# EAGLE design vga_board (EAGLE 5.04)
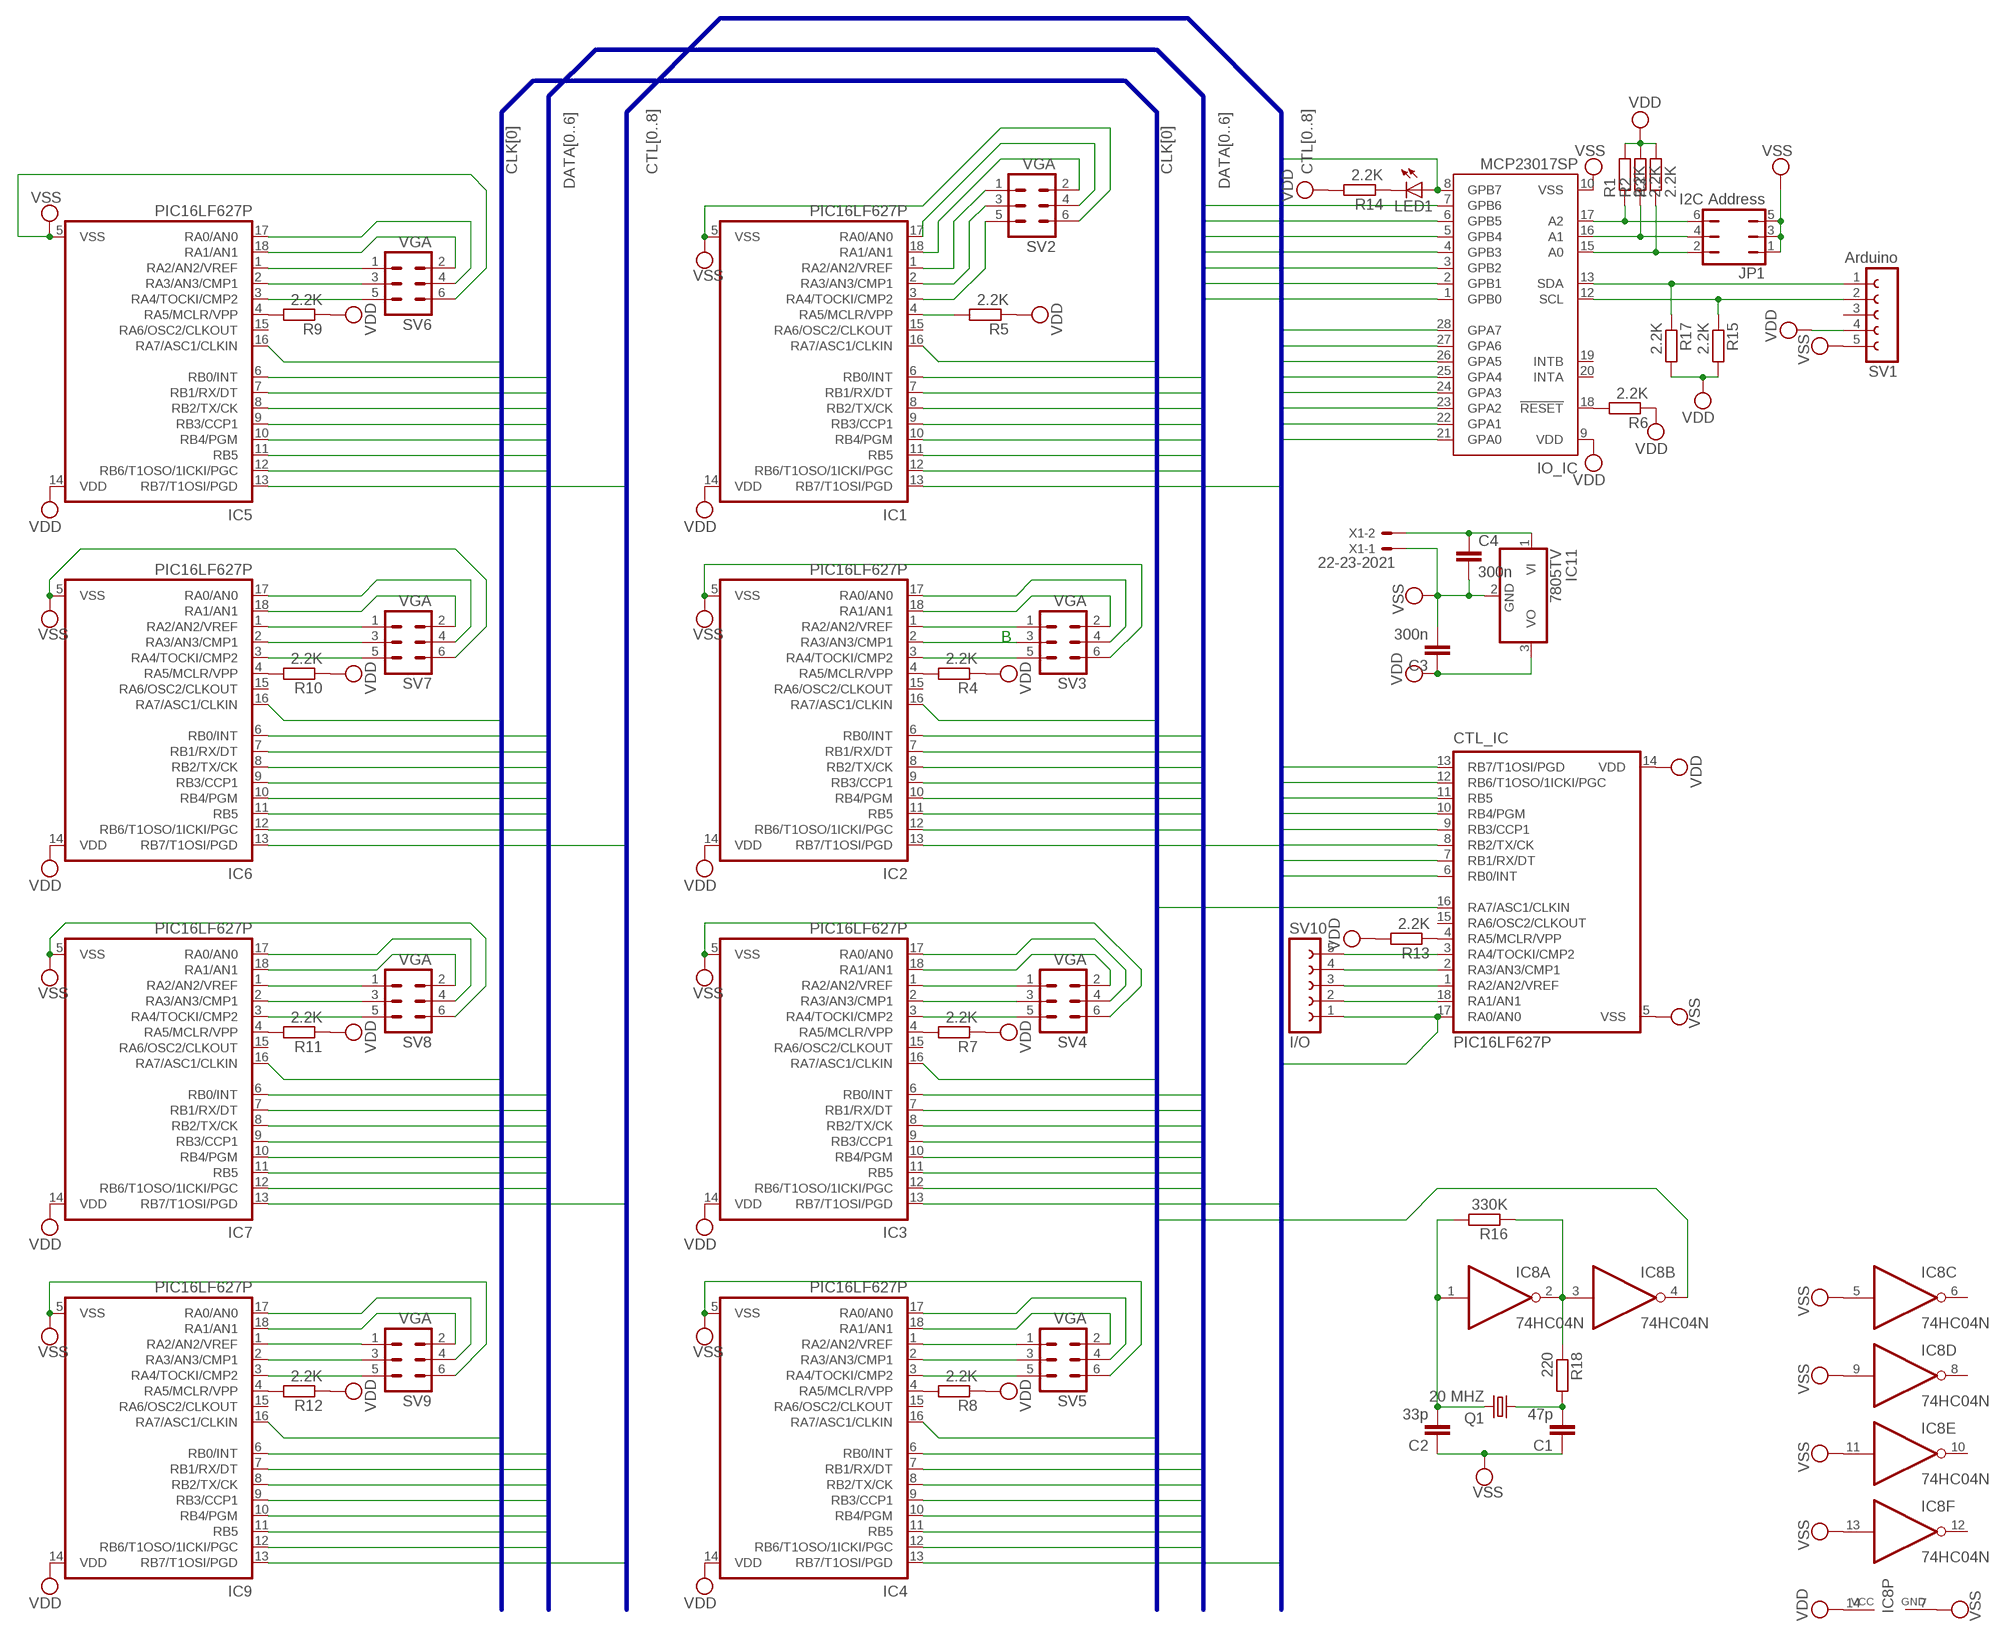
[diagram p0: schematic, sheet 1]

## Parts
C1  47p  C-EU025-024X044  [C025-024X044]
C2  33p  C-EU025-024X044  [C025-024X044]
C3  300n  C-EU025-024X044  [C025-024X044]
C4  300n  C-EU025-024X044  [C025-024X044]
CTL_IC  PIC16LF627P  [DIL18]
IC1  PIC16LF627P  [DIL18]
IC2  PIC16LF627P  [DIL18]
IC3  PIC16LF627P  [DIL18]
IC4  PIC16LF627P  [DIL18]
IC5  PIC16LF627P  [DIL18]
IC6  PIC16LF627P  [DIL18]
IC7  PIC16LF627P  [DIL18]
IC8  74HC04N  [DIL14]
IC9  PIC16LF627P  [DIL18]
IC11  7805TV  [TO220V]
IO_IC  MCP23017SP  [DIL28-3]
JP1  I2C Address  JP3Q  [JP3Q]
LED1  LED3MM  [LED3MM]
Q1  20 MHZ  CRYSTALHC18U-V  [HC18U-V]
R1  2.2K  R-EU_0204/7  [0204/7]
R2  2.2K  R-EU_0204/7  [0204/7]
R3  2.2K  R-EU_0204/7  [0204/7]
R4  2.2K  R-EU_0207/2V  [0207/2V]
R5  2.2K  R-EU_0207/2V  [0207/2V]
R6  2.2K  R-EU_0204/7  [0204/7]
R7  2.2K  R-EU_0207/2V  [0207/2V]
R8  2.2K  R-EU_0207/2V  [0207/2V]
R9  2.2K  R-EU_0207/2V  [0207/2V]
R10  2.2K  R-EU_0207/2V  [0207/2V]
R11  2.2K  R-EU_0207/2V  [0207/2V]
R12  2.2K  R-EU_0207/2V  [0207/2V]
R13  2.2K  R-EU_0207/2V  [0207/2V]
R14  2.2K  R-EU_0204/7  [0204/7]
R15  2.2K  R-EU_0207/2V  [0207/2V]
R16  330K  R-EU_0207/2V  [0207/2V]
R17  2.2K  R-EU_0207/2V  [0207/2V]
R18  220  R-EU_0207/2V  [0207/2V]
SV1  Arduino  FE05-1  [FE05-1]
SV2  VGA  MA03-2  [MA03-2]
SV3  VGA  MA03-2  [MA03-2]
SV4  VGA  MA03-2  [MA03-2]
SV5  VGA  MA03-2  [MA03-2]
SV6  VGA  MA03-2  [MA03-2]
SV7  VGA  MA03-2  [MA03-2]
SV8  VGA  MA03-2  [MA03-2]
SV9  VGA  MA03-2  [MA03-2]
SV10  I/O  FE05-1  [FE05-1]
X1  22-23-2021  [22-23-2021]

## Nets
CLK0: CTL_IC.16(RA7/ASC1/CLKIN) IC1.16(RA7/ASC1/CLKIN) IC2.16(RA7/ASC1/CLKIN) IC3.16(RA7/ASC1/CLKIN) IC4.16(RA7/ASC1/CLKIN) IC5.16(RA7/ASC1/CLKIN) IC6.16(RA7/ASC1/CLKIN) IC7.16(RA7/ASC1/CLKIN) IC8.4(B:O) IC9.16(RA7/ASC1/CLKIN)
CTL0: CTL_IC.6(RB0/INT) IC1.13(RB7/T1OSI/PGD) IO_IC.21(GPA0)
CTL1: CTL_IC.7(RB1/RX/DT) IC2.13(RB7/T1OSI/PGD) IO_IC.22(GPA1)
CTL2: CTL_IC.8(RB2/TX/CK) IC3.13(RB7/T1OSI/PGD) IO_IC.23(GPA2)
CTL3: CTL_IC.9(RB3/CCP1) IC4.13(RB7/T1OSI/PGD) IO_IC.24(GPA3)
CTL4: CTL_IC.10(RB4/PGM) IC5.13(RB7/T1OSI/PGD) IO_IC.25(GPA4)
CTL5: CTL_IC.11(RB5) IC6.13(RB7/T1OSI/PGD) IO_IC.26(GPA5)
CTL6: CTL_IC.12(RB6/T1OSO/1ICKI/PGC) IC7.13(RB7/T1OSI/PGD) IO_IC.27(GPA6)
CTL7: CTL_IC.13(RB7/T1OSI/PGD) IC9.13(RB7/T1OSI/PGD) IO_IC.28(GPA7)
CTL8: CTL_IC.17(RA0/AN0) IO_IC.8(GPB7) LED1.A SV10.1
DATA0: IC1.6(RB0/INT) IC2.6(RB0/INT) IC3.6(RB0/INT) IC4.6(RB0/INT) IC5.6(RB0/INT) IC6.6(RB0/INT) IC7.6(RB0/INT) IC9.6(RB0/INT) IO_IC.1(GPB0)
DATA1: IC1.7(RB1/RX/DT) IC2.7(RB1/RX/DT) IC3.7(RB1/RX/DT) IC4.7(RB1/RX/DT) IC5.7(RB1/RX/DT) IC6.7(RB1/RX/DT) IC7.7(RB1/RX/DT) IC9.7(RB1/RX/DT) IO_IC.2(GPB1)
DATA2: IC1.8(RB2/TX/CK) IC2.8(RB2/TX/CK) IC3.8(RB2/TX/CK) IC4.8(RB2/TX/CK) IC5.8(RB2/TX/CK) IC6.8(RB2/TX/CK) IC7.8(RB2/TX/CK) IC9.8(RB2/TX/CK) IO_IC.3(GPB2)
DATA3: IC1.9(RB3/CCP1) IC2.9(RB3/CCP1) IC3.9(RB3/CCP1) IC4.9(RB3/CCP1) IC5.9(RB3/CCP1) IC6.9(RB3/CCP1) IC7.9(RB3/CCP1) IC9.9(RB3/CCP1) IO_IC.4(GPB3)
DATA4: IC1.10(RB4/PGM) IC2.10(RB4/PGM) IC3.10(RB4/PGM) IC4.10(RB4/PGM) IC5.10(RB4/PGM) IC6.10(RB4/PGM) IC7.10(RB4/PGM) IC9.10(RB4/PGM) IO_IC.5(GPB4)
DATA5: IC1.11(RB5) IC2.11(RB5) IC3.11(RB5) IC4.11(RB5) IC5.11(RB5) IC6.11(RB5) IC7.11(RB5) IC9.11(RB5) IO_IC.6(GPB5)
DATA6: IC1.12(RB6/T1OSO/1ICKI/PGC) IC2.12(RB6/T1OSO/1ICKI/PGC) IC3.12(RB6/T1OSO/1ICKI/PGC) IC4.12(RB6/T1OSO/1ICKI/PGC) IC5.12(RB6/T1OSO/1ICKI/PGC) IC6.12(RB6/T1OSO/1ICKI/PGC) IC7.12(RB6/T1OSO/1ICKI/PGC) IC9.12(RB6/T1OSO/1ICKI/PGC) IO_IC.7(GPB6)
IC8: IC9.2(RA3/AN3/CMP1) SV9.3
N$1: IO_IC.17(A2) JP1.6 R1.1
N$2: IO_IC.16(A1) JP1.4 R2.1
N$3: IO_IC.15(A0) JP1.2 R3.1
N$4: IC2.4(RA5/MCLR/VPP) R4.2
N$5: IO_IC.13(SDA) R17.1 SV1.1
N$6: IC2.3(RA4/TOCKI/CMP2) SV3.5
N$7: C1.2 Q1.1 R18.2
N$8: IO_IC.18(!RESET) R6.2
N$9: IO_IC.12(SCL) R15.1 SV1.2
N$10: IC1.4(RA5/MCLR/VPP) R5.2
N$11: IC1.3(RA4/TOCKI/CMP2) SV2.5
N$12: IC1.2(RA3/AN3/CMP1) SV2.3
N$13: IC1.1(RA2/AN2/VREF) SV2.1
N$14: IC1.18(RA1/AN1) SV2.2
N$15: IC2.2(RA3/AN3/CMP1) SV3.3
N$16: IC2.1(RA2/AN2/VREF) SV3.1
N$17: IC2.18(RA1/AN1) SV3.2
N$18: IC2.17(RA0/AN0) SV3.4
N$19: IC3.4(RA5/MCLR/VPP) R7.2
N$20: IC3.3(RA4/TOCKI/CMP2) SV4.5
N$21: IC3.2(RA3/AN3/CMP1) SV4.3
N$22: IC3.1(RA2/AN2/VREF) SV4.1
N$23: IC3.18(RA1/AN1) SV4.2
N$24: IC3.17(RA0/AN0) SV4.4
N$25: IC4.4(RA5/MCLR/VPP) R8.2
N$26: IC4.3(RA4/TOCKI/CMP2) SV5.5
N$27: IC4.2(RA3/AN3/CMP1) SV5.3
N$28: IC4.1(RA2/AN2/VREF) SV5.1
N$29: IC4.18(RA1/AN1) SV5.2
N$30: IC4.17(RA0/AN0) SV5.4
N$31: IC5.4(RA5/MCLR/VPP) R9.2
N$32: CTL_IC.4(RA5/MCLR/VPP) R13.1
N$33: IC5.3(RA4/TOCKI/CMP2) SV6.5
N$34: IC5.2(RA3/AN3/CMP1) SV6.3
N$35: IC5.1(RA2/AN2/VREF) SV6.1
N$36: IC5.18(RA1/AN1) SV6.2
N$37: IC6.4(RA5/MCLR/VPP) R10.2
N$38: IC6.3(RA4/TOCKI/CMP2) SV7.5
N$39: IC6.2(RA3/AN3/CMP1) SV7.3
N$40: IC6.1(RA2/AN2/VREF) SV7.1
N$41: IC6.18(RA1/AN1) SV7.2
N$42: IC6.17(RA0/AN0) SV7.4
N$43: IC7.4(RA5/MCLR/VPP) R11.2
N$44: IC7.3(RA4/TOCKI/CMP2) SV8.5
N$45: IC7.2(RA3/AN3/CMP1) SV8.3
N$46: IC7.1(RA2/AN2/VREF) SV8.1
N$47: IC7.18(RA1/AN1) SV8.2
N$48: IC7.17(RA0/AN0) SV8.4
N$49: IC9.4(RA5/MCLR/VPP) R12.2
N$50: IC9.3(RA4/TOCKI/CMP2) SV9.5
N$51: C2.2 IC8.1(A:I) Q1.2 R16.2
N$52: IC9.1(RA2/AN2/VREF) SV9.1
N$53: IC9.18(RA1/AN1) SV9.2
N$54: IC9.17(RA0/AN0) SV9.4
N$55: IC5.17(RA0/AN0) SV6.4
N$56: IC8.2(A:O) IC8.3(B:I) R16.1 R18.1
N$57: CTL_IC.18(RA1/AN1) SV10.2
N$58: CTL_IC.1(RA2/AN2/VREF) SV10.3
N$59: CTL_IC.2(RA3/AN3/CMP1) SV10.4
N$60: CTL_IC.3(RA4/TOCKI/CMP2) SV10.5
N$61 [high]: C4.1 IC11.1(VI) X1.2
N$62: LED1.K(C) R14.1
N$68: IC1.17(RA0/AN0) SV2.4
VDD: C3.1 CTL_IC.14(VDD) IC1.14(VDD) IC2.14(VDD) IC3.14(VDD) IC4.14(VDD) IC5.14(VDD) IC6.14(VDD) IC7.14(VDD) IC8.14(P:VCC) IC9.14(VDD) IC11.3(VO) IO_IC.9(VDD) R1.2 R2.2 R3.2 R4.1 R5.1 R6.1 R7.1 R8.1 R9.1 R10.1 R11.1 R12.1 R13.2 R14.2 R15.2 R17.2 SV1.4
VSS: C1.1 C2.1 C3.2 C4.2 CTL_IC.5(VSS) IC1.5(VSS) IC2.5(VSS) IC3.5(VSS) IC4.5(VSS) IC5.5(VSS) IC6.5(VSS) IC7.5(VSS) IC8.5(C:I) IC8.7(P:GND) IC8.9(D:I) IC8.11(E:I) IC8.13(F:I) IC9.5(VSS) IC11.2(GND) IO_IC.10(VSS) JP1.1 JP1.3 JP1.5 SV1.5 SV2.6 SV3.6 SV4.6 SV5.6 SV6.6 SV7.6 SV8.6 SV9.6 X1.1
Unconnected: CTL_IC.15(RA6/OSC2/CLKOUT) IC1.15(RA6/OSC2/CLKOUT) IC2.15(RA6/OSC2/CLKOUT) IC3.15(RA6/OSC2/CLKOUT) IC4.15(RA6/OSC2/CLKOUT) IC5.15(RA6/OSC2/CLKOUT) IC6.15(RA6/OSC2/CLKOUT) IC7.15(RA6/OSC2/CLKOUT) IC8.6(C:O) IC8.8(D:O) IC8.10(E:O) IC8.12(F:O) IC9.15(RA6/OSC2/CLKOUT) IO_IC.19(INTB) IO_IC.20(INTA) SV1.3

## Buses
DATA[0..6]
CTL[0..8]
CLK[0]

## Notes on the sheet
- B

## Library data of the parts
C1-C4 = rcl:C-EU: CAPACITOR, European symbol
CTL_IC IC1-IC7 IC9 = microchip:PIC16*F62: FLASH-Based 8-Bit CMOS Microcontroller Source: http://ww1.microchip.com/downloads/en/DeviceDoc/40300C.pdf
IC8 = 74xx-eu:74*04: Hex INVERTER
IC11 = linear:78*: Positive VOLTAGE REGULATOR Source: http://cache.national.com/ds/LM/LM78L05.pdf http://www.fairchildsemi.com/ds/LM/LM7805.pdf
IO_IC = microchip:MCP23017: http://ww1.microchip.com/downloads/en/DeviceDoc/21952a.pdf Source: http://ww1.microchip.com/downloads/en/DeviceDoc/21952a.pdf
JP1 = jumper:JP3Q: JUMPER
LED1 = led:LED: LED
Q1 = crystal:CRYSTAL: CRYSTAL
R1-R18 = resistor:R-EU_: RESISTOR, European symbol
SV1 SV10 = con-lsta:FE05-1: FEMALE HEADER
SV2-SV9 = con-lstb:MA03-2: PIN HEADER
X1 = con-molex:22-23-2021: .100" (2.54mm) Center Header - 2 Pin

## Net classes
1 high: width 1.016 mm, clearance 0.508 mm

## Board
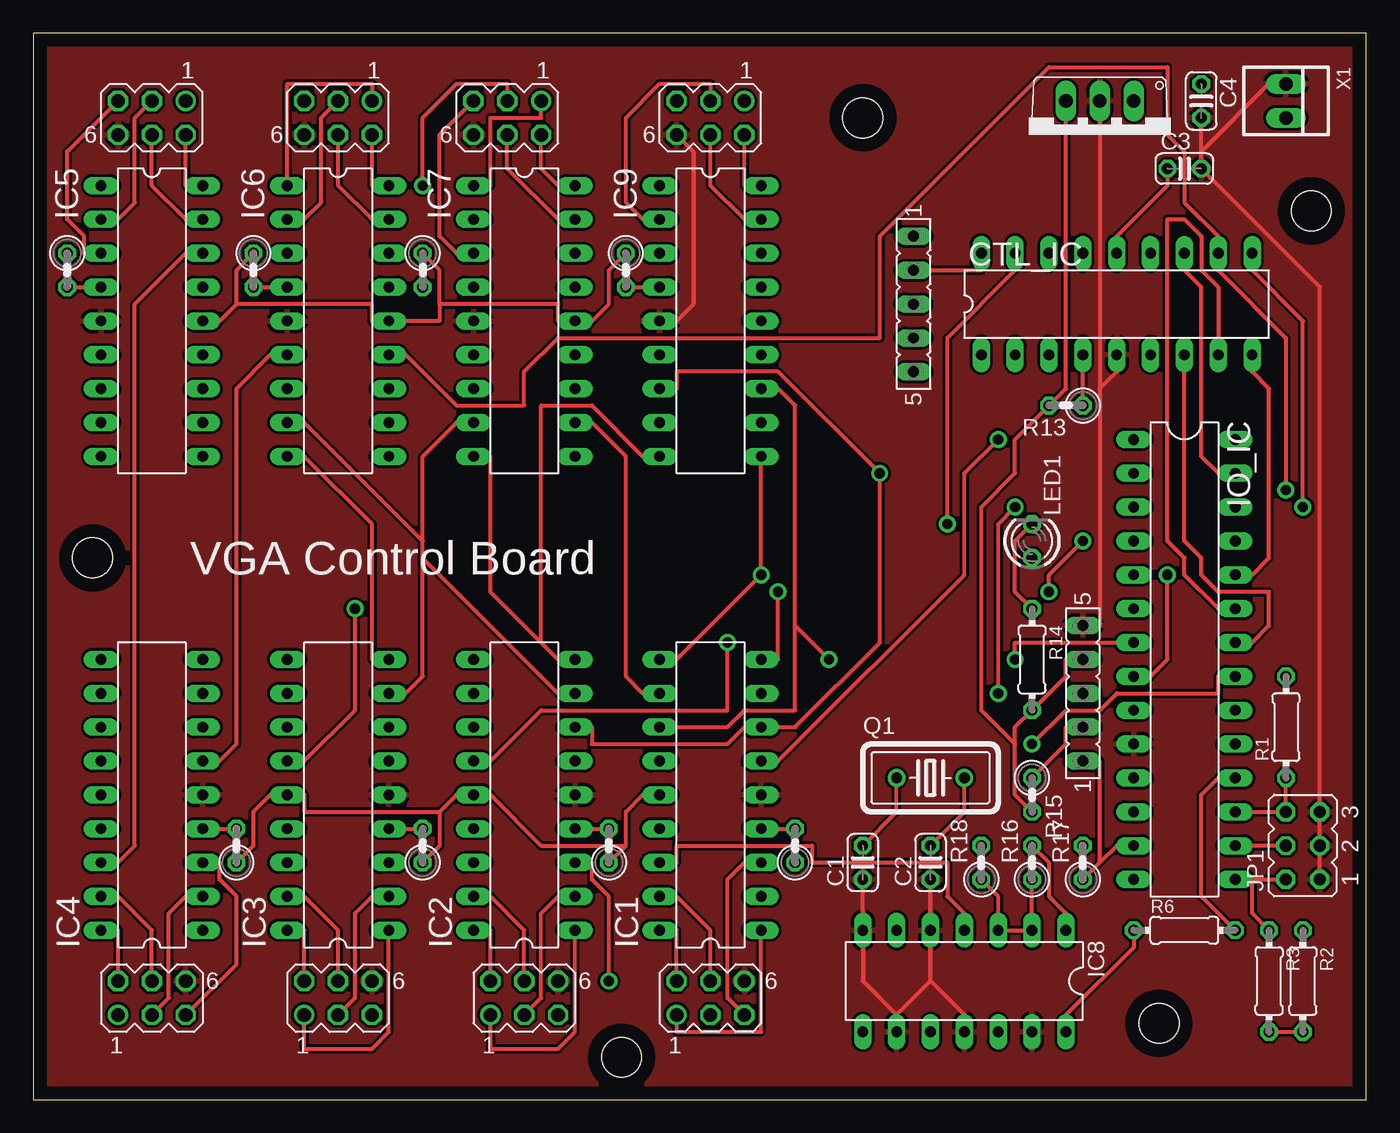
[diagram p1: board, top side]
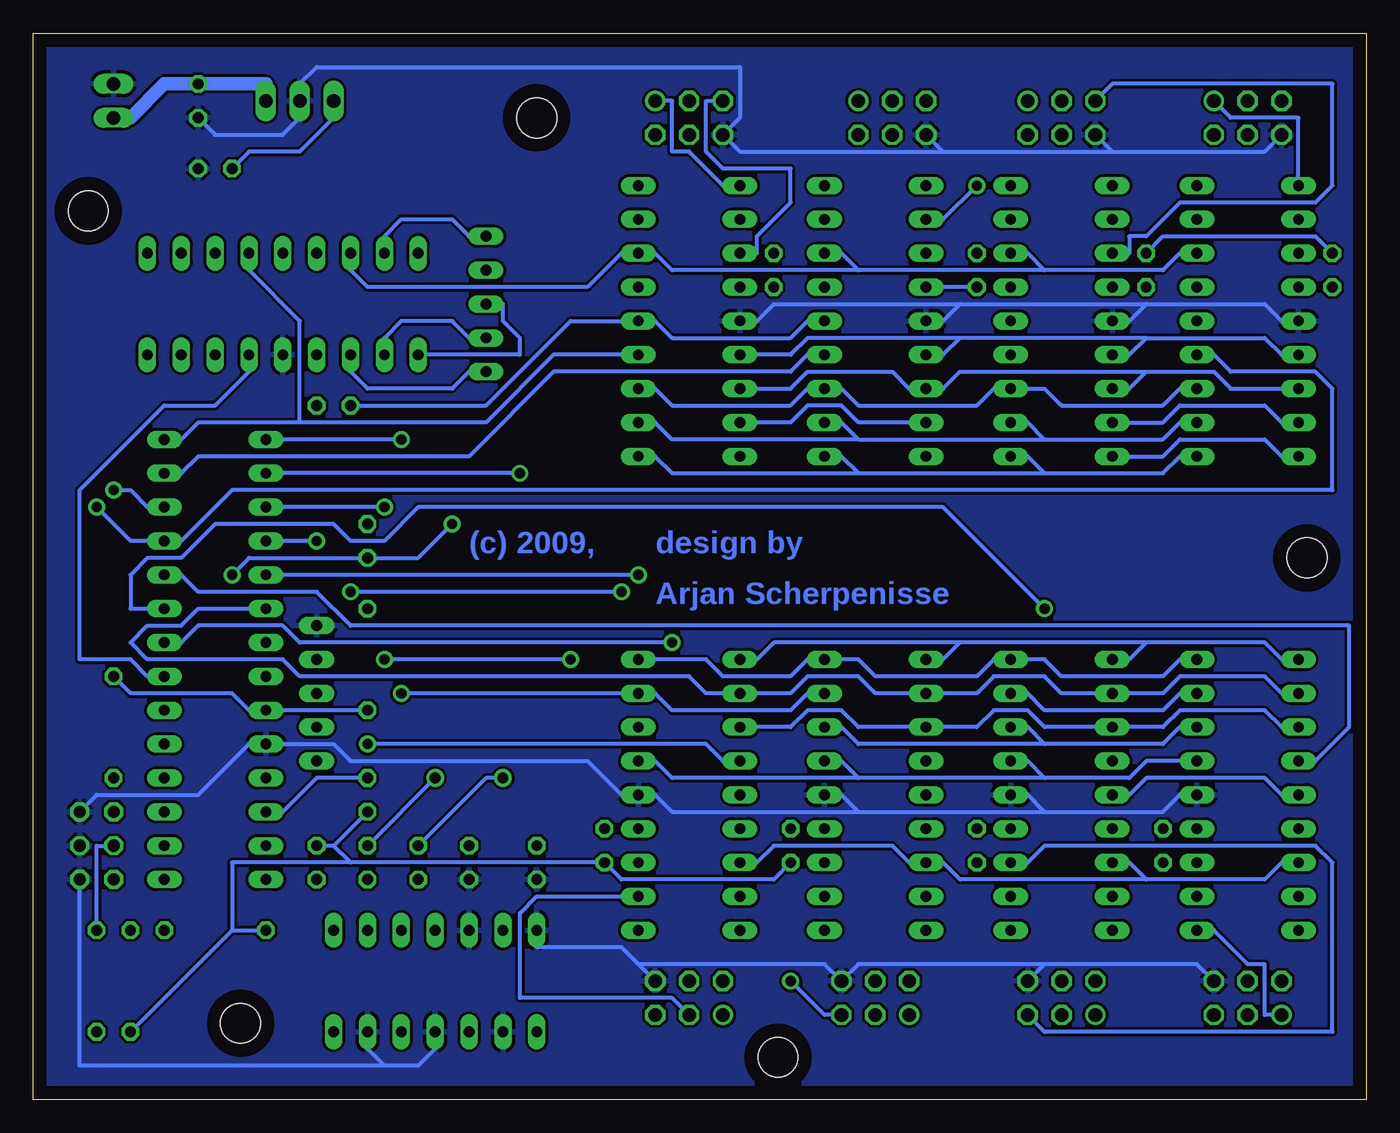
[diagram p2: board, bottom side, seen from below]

Size 100 x 80 mm. Coordinates in mm from the lower left corner, seen from the top.
Outline: 0,0 100,0 100,80 0,80 0,0
Copper layers (1*16): Top 0.035mm / dielectric 1.5mm / Bottom 0.035mm
Design rules "default *": minimum track width 12mil, minimum drill 30mil, track to track 8mil, track to pad 8mil, pad to pad 8mil, via to via 8mil, smd to smd 8mil, copper to edge 40mil, drill to drill 8mil, minimum pad ring 10mil, minimum via ring 8mil, stop-mask expansion 4mil, vias tented up to drill 0mil, thermal gap 10mil
Holes 3 mm at 84.45,5.71 44.13,3.17 95.89,66.67 62.23,73.66 4.45,40.64

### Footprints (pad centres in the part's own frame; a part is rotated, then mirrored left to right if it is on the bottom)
C025-024X044 = drill 0.813 octagon: 1 -1.27,0; 2 1.27,0
DIL18 = drill 0.813 long: 1 -10.16,-3.81; 2 -7.62,-3.81; 3 -5.08,-3.81; 4 -2.54,-3.81; 5 0,-3.81; 6 2.54,-3.81; 7 5.08,-3.81; 8 7.62,-3.81; 9 10.16,-3.81; 10 10.16,3.81; 11 7.62,3.81; 12 5.08,3.81; 13 2.54,3.81; 14 0,3.81; 15 -2.54,3.81; 16 -5.08,3.81; 17 -7.62,3.81; 18 -10.16,3.81
DIL14 = drill 0.813 long: 1 -7.62,-3.81; 2 -5.08,-3.81; 3 -2.54,-3.81; 4 0,-3.81; 5 2.54,-3.81; 6 5.08,-3.81; 7 7.62,-3.81; 8 7.62,3.81; 9 5.08,3.81; 10 2.54,3.81; 11 0,3.81; 12 -2.54,3.81; 13 -5.08,3.81; 14 -7.62,3.81
TO220V = drill 1.016 long: 1 -2.54,-2.54; 2 0,-2.54; 3 2.54,-2.54
DIL28-3 = drill 0.813 long: 1 -16.51,-3.81; 2 -13.97,-3.81; 3 -11.43,-3.81; 4 -8.89,-3.81; 5 -6.35,-3.81; 6 -3.81,-3.81; 7 -1.27,-3.81; 8 1.27,-3.81; 9 3.81,-3.81; 10 6.35,-3.81; 11 8.89,-3.81; 12 11.43,-3.81; 13 13.97,-3.81; 14 16.51,-3.81; 15 16.51,3.81; 16 13.97,3.81; 17 11.43,3.81; 18 8.89,3.81; 19 6.35,3.81; 20 3.81,3.81; 21 1.27,3.81; 22 -1.27,3.81; 23 -3.81,3.81; 24 -6.35,3.81; 25 -8.89,3.81; 26 -11.43,3.81; 27 -13.97,3.81; 28 -16.51,3.81
JP3Q = drill 0.914 octagon: 1 -2.54,-1.27; 2 -2.54,1.27; 3 0,-1.27; 4 0,1.27; 5 2.54,-1.27; 6 2.54,1.27
LED3MM = drill 0.813 octagon: A -1.27,0; K 1.27,0
HC18U-V = drill 0.813 round: 1 -2.54,0; 2 2.54,0
0204/7 = drill 0.813 octagon: 1 -3.81,0; 2 3.81,0
0207/2V = drill 0.813 octagon: 1 -1.27,0; 2 1.27,0
FE05-1 = drill 0.813 long: 1 -5.08,0; 2 -2.54,0; 3 0,0; 4 2.54,0; 5 5.08,0
MA03-2 = drill 1.016 round: 1 -2.54,-1.27 | drill 1.016 octagon: 2 -2.54,1.27; 3 0,-1.27; 4 0,1.27; 5 2.54,-1.27; 6 2.54,1.27
22-23-2021 = drill 1 long: 1 -1.27,0; 2 1.27,0

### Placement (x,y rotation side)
C1  62.23,17.78 90 top
C2  67.31,17.78 90 top
C3  86.36,69.85 0 top
C4  87.63,74.93 270 top
CTL_IC  81.28,59.69 0 top
IC1  50.8,22.86 90 top
IC2  36.83,22.86 90 top
IC3  22.86,22.86 90 top
IC4  8.89,22.86 90 top
IC5  8.89,58.42 270 top
IC6  22.86,58.42 270 top
IC7  36.83,58.42 270 top
IC8  69.85,8.89 180 top
IC9  50.8,58.42 270 top
IC11  80.01,72.39 180 top
IO_IC  86.36,33.02 270 top
JP1  95.25,19.05 90 top
LED1  74.93,41.91 90 top
Q1  67.31,24.13 0 top
R1  93.98,27.94 90 top
R2  95.25,8.89 270 top
R3  92.71,8.89 270 top
R4  43.18,19.05 90 top
R5  57.15,19.05 90 top
R6  86.36,12.7 0 top
R7  29.21,19.05 90 top
R8  15.24,19.05 90 top
R9  2.54,62.23 270 top
R10  16.51,62.23 270 top
R11  29.21,62.23 270 top
R12  44.45,62.23 270 top
R13  77.47,52.07 180 top
R14  74.93,33.02 270 top
R15  74.93,22.86 270 top
R16  74.93,17.78 90 top
R17  78.74,17.78 90 top
R18  71.12,17.78 90 top
SV1  78.74,30.48 90 top
SV2  50.8,7.62 0 top
SV3  36.83,7.62 0 top
SV4  22.86,7.62 0 top
SV5  8.89,7.62 0 top
SV6  8.89,73.66 180 top
SV7  22.86,73.66 180 top
SV8  35.56,73.66 180 top
SV9  50.8,73.66 180 top
SV10  66.04,59.69 270 top
X1  93.98,74.93 270 top

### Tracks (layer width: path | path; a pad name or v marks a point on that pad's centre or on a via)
CLK0
  Top 0.305: IC8.4 69.85,13.97 68.58,15.24 68.58,17.78 58.42,17.78 58.42,19.05 48.26,19.05 48.26,17.78 IC1.16 | IC5.16 11.43,63.5 7.62,59.69 7.62,19.05 6.35,17.78 IC4.16
  Bottom 0.305: 24.13,62.23 15.24,62.23 13.97,63.5 IC5.16 | 24.13,62.23 25.4,63.5 IC6.16 | 38.1,62.23 39.37,63.5 IC7.16 | 24.13,62.23 38.1,62.23 | 38.1,62.23 52.07,62.23 53.34,63.5 IC9.16 55.88,63.5 58.42,60.96 74.93,60.96 76.2,62.23 CTL_IC.16 | 16.51,16.51 7.62,16.51 6.35,17.78 IC4.16 | 16.51,16.51 17.78,17.78 IC3.16 | 16.51,16.51 30.48,16.51 31.75,17.78 IC2.16 34.29,17.78 35.56,19.05 44.45,19.05 45.72,17.78 IC1.16
CTL0  (via drill 0.76 pad 1.27)
  Top 0.305: v74.93,26.67 77.47,29.21 80.01,29.21 81.28,30.48 88.9,30.48 88.9,31.75 IO_IC.21
  Bottom 0.305: v74.93,26.67 49.53,26.67 48.26,25.4 IC1.13 | CTL_IC.6 83.82,54.61 86.36,52.07 90.17,52.07 96.52,45.72 96.52,33.02 92.71,33.02 91.44,31.75 IO_IC.21
CTL1  (via drill 0.76 pad 1.27)
  Top 0.305: v52.07,34.29 52.07,29.21 38.1,29.21 34.29,25.4 IC2.13 | CTL_IC.7 86.36,41.91 87.63,40.64 87.63,39.37 88.9,38.1 92.71,38.1 92.71,35.56 91.44,34.29 IO_IC.22
  Bottom 0.305: v52.07,34.29 80.01,34.29 81.28,35.56 87.63,35.56 88.9,34.29 IO_IC.22
CTL2  (via drill 0.76 pad 1.27)
  Top 0.305: v24.13,36.83 24.13,29.21 20.32,25.4 IC3.13 | CTL_IC.8 88.9,60.96 87.63,62.23 87.63,64.77 86.36,66.04 85.09,66.04 85.09,41.91 86.36,40.64 86.36,39.37 88.9,36.83 IO_IC.23
  Bottom 0.305: v24.13,36.83 31.75,44.45 71.12,44.45 73.66,41.91 76.2,41.91 77.47,43.18 86.36,43.18 88.9,40.64 91.44,40.64 92.71,39.37 92.71,36.83 IO_IC.23
CTL3
  Top 0.305: CTL_IC.9 91.44,54.61 92.71,53.34 92.71,40.64 91.44,39.37 IO_IC.24
  Bottom 0.305: IC4.13 3.81,25.4 1.27,27.94 1.27,35.56 76.2,35.56 78.74,38.1 87.63,38.1 88.9,39.37 IO_IC.24
CTL4  (via drill 0.76 pad 1.27)
  Top 0.305: v95.25,44.45 95.25,58.42 91.44,62.23 CTL_IC.10
  Bottom 0.305: IC5.13 11.43,55.88 10.16,54.61 3.81,54.61 2.54,53.34 2.54,45.72 85.09,45.72 88.9,41.91 IO_IC.25 92.71,41.91 v95.25,44.45
CTL5  (via drill 0.76 pad 1.27)
  Top 0.305: IC6.13 27.94,55.88 31.75,52.07 36.83,52.07 36.83,54.61 39.37,57.15 63.5,57.15 63.5,64.77 76.2,77.47 85.09,77.47 85.09,72.39 86.36,71.12 86.36,67.31 88.9,64.77 CTL_IC.11 88.9,62.23 93.98,57.15 v93.98,45.72
  Bottom 0.305: v93.98,45.72 92.71,45.72 91.44,44.45 IO_IC.26
CTL6
  Top 0.305: CTL_IC.12 86.36,62.23 87.63,60.96 87.63,48.26 88.9,46.99 IO_IC.27
  Bottom 0.305: IC7.13 41.91,55.88 43.18,54.61 60.96,54.61 67.31,48.26 87.63,48.26 88.9,46.99 IO_IC.27
CTL7
  Bottom 0.305: 80.01,50.8 87.63,50.8 88.9,49.53 IO_IC.28 | 80.01,50.8 66.04,50.8 60.96,55.88 IC9.13 | 80.01,50.8 80.01,58.42 83.82,62.23 CTL_IC.13
CTL8  (via drill 0.76 pad 1.27)
  Top 0.305: v85.09,39.37 85.09,33.02 83.82,31.75 IO_IC.8 | v68.58,43.18 68.58,57.15 73.66,62.23 CTL_IC.17
  Bottom 0.305: SV10.1 67.31,64.77 68.58,66.04 72.39,66.04 73.66,64.77 CTL_IC.17 | v85.09,39.37 83.82,40.64 LED1.A 71.12,40.64 v68.58,43.18
DATA0  (via drill 0.76 pad 1.27)
  Top 0.305: v72.39,49.53 69.85,46.99 69.85,39.37 55.88,25.4 IC1.6 | IC6.6 17.78,55.88 15.24,53.34 15.24,26.67 13.97,25.4 IC4.6
  Bottom 0.305: 16.51,57.15 7.62,57.15 6.35,55.88 IC5.6 | 16.51,57.15 17.78,55.88 IC6.6 | 30.48,57.15 31.75,55.88 IC7.6 | 16.51,57.15 30.48,57.15 | 30.48,57.15 41.91,57.15 43.18,55.88 IC9.6 | 24.13,24.13 17.78,24.13 16.51,25.4 IC4.6 | 24.13,24.13 25.4,25.4 IC3.6 | 38.1,24.13 39.37,25.4 IC2.6 | 24.13,24.13 38.1,24.13 | 38.1,24.13 52.07,24.13 53.34,25.4 IC1.6 | v72.39,49.53 IO_IC.1
DATA1  (via drill 0.76 pad 1.27)
  Top 0.305: IC2.7 41.91,27.94 41.91,26.67 52.07,26.67 53.34,27.94 IC1.7 57.15,27.94 63.5,34.29 v63.5,46.99 55.88,54.61 48.26,54.61 48.26,53.34 IC9.7
  Bottom 0.305: 24.13,26.67 15.24,26.67 13.97,27.94 IC4.7 | 24.13,26.67 25.4,27.94 IC3.7 | 24.13,26.67 38.1,26.67 39.37,27.94 IC2.7 | 16.51,54.61 11.43,54.61 10.16,53.34 IC5.7 | 16.51,54.61 17.78,53.34 IC6.7 | 16.51,54.61 30.48,54.61 31.75,53.34 IC7.7 34.29,53.34 35.56,54.61 41.91,54.61 43.18,53.34 IC9.7 | v63.5,46.99 IO_IC.2
DATA2  (via drill 0.76 pad 1.27)
  Top 0.305: v73.66,44.45 72.39,43.18 v72.39,30.48 | 29.21,40.64 29.21,31.75 27.94,30.48 IC3.8 | 29.21,40.64 29.21,41.91 | 29.21,41.91 29.21,48.26 31.75,50.8 IC7.8 | 29.21,41.91 20.32,50.8 IC6.8 | 29.21,40.64 39.37,30.48 IC2.8
  Bottom 0.305: IC2.8 41.91,30.48 43.18,29.21 52.07,29.21 53.34,30.48 IC1.8 v72.39,30.48 | v73.66,44.45 IO_IC.3 | IC5.8 6.35,50.8 7.62,52.07 13.97,52.07 15.24,50.8 IC6.8 | IC4.8 13.97,30.48 15.24,29.21 24.13,29.21 25.4,30.48 IC3.8 | IC9.8 43.18,50.8 41.91,52.07 39.37,52.07 38.1,50.8 IC7.8
DATA3  (via drill 0.76 pad 1.27)
  Top 0.305: 38.1,34.29 34.29,38.1 34.29,48.26 IC7.9 | 38.1,34.29 39.37,33.02 IC2.9 | v78.74,41.91 76.2,39.37 v76.2,38.1 | v55.88,38.1 55.88,33.02 IC1.9 | 38.1,34.29 38.1,52.07 41.91,52.07 45.72,48.26 IC9.9 | IC6.9 20.32,48.26 25.4,43.18 25.4,33.02 IC3.9
  Bottom 0.305: IC5.9 6.35,48.26 7.62,49.53 13.97,49.53 15.24,48.26 IC6.9 | IC4.9 13.97,33.02 15.24,31.75 22.86,31.75 24.13,33.02 IC3.9 27.94,33.02 29.21,31.75 36.83,31.75 38.1,33.02 IC2.9 41.91,33.02 43.18,31.75 48.26,31.75 49.53,33.02 IC1.9 | v55.88,38.1 v76.2,38.1 | v78.74,41.91 IO_IC.4
DATA4  (via drill 0.76 pad 1.27)
  Top 0.305: IC9.10 v54.61,39.37 48.26,33.02 IC1.10
  Bottom 0.305: 16.51,34.29 7.62,34.29 6.35,33.02 IC4.10 | 16.51,34.29 17.78,33.02 IC3.10 | 30.48,34.29 31.75,33.02 IC2.10 | 16.51,34.29 30.48,34.29 | 30.48,34.29 44.45,34.29 45.72,33.02 IC1.10 | 24.13,46.99 15.24,46.99 13.97,48.26 IC5.10 | 24.13,46.99 25.4,48.26 IC6.10 | 38.1,46.99 39.37,48.26 IC7.10 | 38.1,46.99 24.13,46.99 | 38.1,46.99 52.07,46.99 53.34,48.26 IC9.10 | v54.61,39.37 IO_IC.5
DATA5
  Top 0.305: IC7.11 41.91,50.8 44.45,48.26 44.45,31.75 45.72,30.48 IC1.11
  Bottom 0.305: 24.13,49.53 15.24,49.53 13.97,50.8 IC5.11 | 24.13,49.53 25.4,50.8 IC6.11 | 38.1,49.53 39.37,50.8 IC7.11 | 38.1,49.53 24.13,49.53 | 38.1,49.53 52.07,49.53 53.34,50.8 IC9.11 | IC4.11 6.35,30.48 7.62,31.75 13.97,31.75 15.24,30.48 IC3.11 22.86,30.48 24.13,31.75 27.94,31.75 29.21,30.48 IC2.11 36.83,30.48 38.1,31.75 41.91,31.75 43.18,30.48 IC1.11 49.53,30.48 50.8,31.75 80.01,31.75 81.28,33.02 91.44,33.02 92.71,34.29 91.44,35.56 88.9,35.56 87.63,36.83 IO_IC.6
DATA6  (via drill 0.76 pad 1.27)
  Top 0.305: v73.66,33.02 73.66,34.29 IO_IC.7 | 57.15,35.56 v59.69,33.02 | 57.15,35.56 57.15,52.07 55.88,53.34 IC9.12 | 57.15,35.56 57.15,29.21 53.34,29.21 52.07,27.94 IC1.12
  Bottom 0.305: IC4.12 6.35,27.94 7.62,29.21 13.97,29.21 15.24,27.94 IC3.12 24.13,27.94 25.4,29.21 27.94,29.21 29.21,27.94 IC2.12 38.1,27.94 39.37,29.21 41.91,29.21 43.18,27.94 IC1.12 | IC5.12 13.97,53.34 15.24,52.07 22.86,52.07 24.13,53.34 IC6.12 27.94,53.34 29.21,52.07 38.1,52.07 39.37,53.34 IC7.12 41.91,53.34 43.18,52.07 52.07,52.07 53.34,53.34 IC9.12 | v59.69,33.02 v73.66,33.02
IC8
  Top 0.305: SV9.3 50.8,76.2 46.99,76.2 44.45,73.66 44.45,67.31 45.72,66.04 IC9.2
N$1
  Top 0.305: IO_IC.17 JP1.6 R1.1
N$2
  Top 0.305: JP1.4 IO_IC.16
  Bottom 0.305: R2.1 95.25,19.05 JP1.4
N$3
  Top 0.305: R3.1 91.44,13.97 91.44,16.51 | 91.44,16.51 JP1.2 | 91.44,16.51 IO_IC.15
N$4
  Top 0.305: IC2.4 R4.2
N$5
  Top 0.305: 80.01,17.78 81.28,19.05 IO_IC.13 | R17.1 80.01,17.78 | 80.01,17.78 80.01,25.4 SV1.1
N$6  (via drill 0.76 pad 1.27)
  Top 0.305: v43.18,8.89 43.18,15.24 41.91,16.51 41.91,17.78 IC2.3
  Bottom 0.305: v43.18,8.89 40.64,6.35 SV3.5
N$7
  Top 0.305: C1.2 64.77,21.59 Q1.1
  Bottom 0.305: R18.2 66.04,24.13 Q1.1
N$8
  Top 0.305: R6.2 87.63,15.24 87.63,22.86 88.9,24.13 IO_IC.18
N$9
  Top 0.305: R15.1 77.47,26.67 77.47,27.94 SV1.2
  Bottom 0.305: R15.1 78.74,24.13 81.28,21.59 IO_IC.12
N$10
  Top 0.305: IC1.4 R5.2
N$11
  Top 0.305: SV2.5 52.07,7.62 52.07,16.51 53.34,17.78 IC1.3
N$12
  Bottom 0.305: SV2.3 52.07,7.62 63.5,7.62 63.5,13.97 62.23,15.24 IC1.2
N$13
  Top 0.305: IC1.1 54.61,5.08 48.26,5.08 SV2.1
N$14
  Top 0.305: SV2.2 48.26,12.7 IC1.18
N$15
  Top 0.305: SV3.3 38.1,7.62 38.1,13.97 39.37,15.24 IC2.2
N$16
  Top 0.305: IC2.1 40.64,5.08 39.37,3.81 34.29,3.81 SV3.1
N$17
  Top 0.305: SV3.2 34.29,12.7 IC2.18
N$18
  Top 0.305: SV3.4 36.83,12.7 34.29,15.24 IC2.17
N$19
  Top 0.305: IC3.4 R7.2
N$20
  Bottom 0.305: SV4.5 24.13,5.08 2.54,5.08 2.54,17.78 3.81,19.05 24.13,19.05 25.4,17.78 IC3.3
N$21
  Top 0.305: SV4.3 24.13,7.62 24.13,13.97 25.4,15.24 IC3.2
N$22
  Top 0.305: IC3.1 26.67,5.08 25.4,3.81 20.32,3.81 SV4.1
N$23
  Top 0.305: SV4.2 20.32,12.7 IC3.18
N$24
  Top 0.305: SV4.4 22.86,12.7 20.32,15.24 IC3.17
N$25
  Top 0.305: IC4.4 R8.2
N$26
  Top 0.305: SV5.5 15.24,10.16 15.24,15.24 13.97,16.51 13.97,17.78 IC4.3
N$27
  Top 0.305: SV5.3 10.16,7.62 10.16,13.97 11.43,15.24 IC4.2
N$28
  Bottom 0.305: SV5.1 7.62,6.35 7.62,10.16 8.89,10.16 11.43,12.7 IC4.1
N$29
  Top 0.305: SV5.2 6.35,12.7 IC4.18
N$30
  Top 0.305: SV5.4 8.89,12.7 6.35,15.24 IC4.17
N$31
  Top 0.305: R9.2 IC5.4
N$32
  Top 0.305: R13.1 CTL_IC.4
N$33
  Top 0.305: SV6.5 2.54,71.12 2.54,66.04 3.81,64.77 3.81,63.5 IC5.3
N$34
  Top 0.305: SV6.3 7.62,73.66 7.62,67.31 6.35,66.04 IC5.2
N$35
  Bottom 0.305: IC5.1 5.08,73.66 10.16,73.66 SV6.1
N$36
  Top 0.305: SV6.2 11.43,68.58 IC5.18
N$37
  Top 0.305: R10.2 IC6.4
N$38
  Bottom 0.305: SV7.5 19.05,76.2 2.54,76.2 2.54,68.58 3.81,67.31 13.97,67.31 16.51,64.77 17.78,64.77 17.78,63.5 IC6.3
N$39
  Top 0.305: SV7.3 21.59,73.66 21.59,67.31 20.32,66.04 IC6.2
N$40
  Top 0.305: IC6.1 19.05,76.2 25.4,76.2 SV7.1
N$41
  Top 0.305: SV7.2 25.4,68.58 IC6.18
N$42
  Top 0.305: SV7.4 22.86,68.58 25.4,66.04 IC6.17
N$43
  Bottom 0.305: R11.2 IC7.4
N$44
  Top 0.305: SV8.5 30.48,72.39 30.48,64.77 31.75,63.5 IC7.3
N$45  (via drill 0.76 pad 1.27)
  Top 0.305: v29.21,68.58 29.21,73.66 31.75,76.2 35.56,76.2 SV8.3
  Bottom 0.305: v29.21,68.58 31.75,66.04 IC7.2
N$46
  Top 0.305: SV8.1 38.1,73.66 34.29,73.66 34.29,68.58 IC7.1
N$47
  Top 0.305: SV8.2 38.1,69.85 39.37,68.58 IC7.18
N$48
  Top 0.305: SV8.4 35.56,69.85 39.37,66.04 IC7.17
N$49
  Top 0.305: R12.2 IC9.4
N$50
  Bottom 0.305: SV9.5 49.53,74.93 49.53,71.12 48.26,69.85 43.18,69.85 43.18,67.31 45.72,64.77 45.72,63.5 IC9.3
N$51
  Top 0.305: C2.2 69.85,21.59 Q1.2 | R16.2 76.2,17.78 76.2,15.24 77.47,13.97 IC8.1
  Bottom 0.305: Q1.2 R16.2
N$52
  Bottom 0.305: SV9.1 52.07,74.93 52.07,71.12 50.8,71.12 48.26,68.58 IC9.1
N$53
  Top 0.305: SV9.2 53.34,68.58 IC9.18
N$54
  Top 0.305: SV9.4 50.8,68.58 53.34,66.04 IC9.17
N$55
  Top 0.305: SV6.4 8.89,68.58 11.43,66.04 IC5.17
N$56
  Top 0.305: R18.1 72.39,15.24 IC8.3 IC8.2 R16.1
N$57
  Top 0.305: SV10.2 71.12,62.23 CTL_IC.18
N$58
  Bottom 0.305: CTL_IC.1 63.5,55.88 63.5,57.15 64.77,58.42 64.77,59.69 SV10.3
N$59
  Bottom 0.305: SV10.4 67.31,57.15 68.58,58.42 72.39,58.42 73.66,57.15 CTL_IC.2
N$60
  Bottom 0.305: SV10.5 67.31,54.61 68.58,53.34 74.93,53.34 76.2,54.61 CTL_IC.3
N$61
  Bottom 1.016: IC11.1 82.55,76.2 C4.1 90.17,76.2 92.71,73.66 X1.2
N$62
  Top 0.305: R14.1 73.66,38.1 73.66,41.91 LED1.K
N$68
  Top 0.305: SV2.4 50.8,12.7 48.26,15.24 IC1.17
VDD
  Top 0.305: C3.1 85.09,68.58 81.28,64.77 CTL_IC.14 | IC11.3 77.47,53.34 R13.2 73.66,49.53 73.66,46.99 71.12,44.45 71.12,29.21 73.66,26.67 | 15.24,59.69 13.97,58.42 IC5.14 | 15.24,59.69 15.24,62.23 R10.1 | 30.48,59.69 30.48,62.23 R11.1 | 30.48,59.69 30.48,58.42 IC6.14 25.4,58.42 25.4,59.69 15.24,59.69 | R12.1 43.18,62.23 43.18,59.69 41.91,58.42 IC7.14 39.37,58.42 39.37,59.69 30.48,59.69 | R7.1 30.48,19.05 30.48,21.59 | 30.48,21.59 31.75,22.86 IC2.14 34.29,22.86 38.1,19.05 44.45,19.05 | R8.1 16.51,19.05 16.51,21.59 17.78,22.86 IC3.14 20.32,22.86 20.32,21.59 30.48,21.59 | R3.2 R2.2 | R6.1 82.55,11.43 77.47,6.35 IC8.14 | SV1.4 77.47,33.02 77.47,31.75 R14.2 73.66,27.94 73.66,26.67 | 44.45,19.05 R4.1 | 44.45,19.05 44.45,21.59 45.72,22.86 IC1.14 | 73.66,26.67 73.66,22.86 R15.2
  Bottom 0.305: C3.1 83.82,71.12 80.01,71.12 77.47,73.66 IC11.3 | R9.1 3.81,64.77 15.24,64.77 R10.1 | IC7.14 41.91,58.42 43.18,57.15 52.07,57.15 53.34,58.42 IC9.14 59.69,58.42 66.04,52.07 R13.2 | IC4.14 6.35,22.86 7.62,24.13 16.51,24.13 17.78,22.86 IC3.14 | 85.09,12.7 R3.2 | 85.09,12.7 R6.1 | R14.2 IO_IC.9 83.82,29.21 85.09,30.48 92.71,30.48 R1.2 | 77.47,19.05 R15.2 | 77.47,19.05 R17.2 | R4.1 44.45,16.51 55.88,16.51 R5.1 76.2,17.78 | 76.2,17.78 77.47,19.05 | 85.09,12.7 85.09,17.78 76.2,17.78
VSS
  Top 0.305: SV9.6 49.53,71.12 49.53,59.69 48.26,58.42 IC9.5 | 87.63,71.12 C4.2 | 87.63,71.12 C3.2 96.52,60.96 JP1.5 JP1.3 JP1.1 | 87.63,71.12 92.71,76.2 X1.1 | 80.01,53.34 80.01,35.56 SV1.5 | 80.01,53.34 81.28,54.61 CTL_IC.5 | IC11.2 80.01,53.34 | C2.1 IC8.5 67.31,8.89 | 67.31,8.89 69.85,6.35 IC8.11 | C1.1 IC8.7 62.23,8.89 64.77,6.35 | 64.77,6.35 67.31,8.89 | 64.77,6.35 IC8.9
  Bottom 0.305: 16.51,59.69 7.62,59.69 6.35,58.42 IC5.5 | 16.51,59.69 17.78,58.42 IC6.5 | 30.48,59.69 31.75,58.42 IC7.5 | 30.48,59.69 16.51,59.69 | 30.48,59.69 44.45,59.69 45.72,58.42 IC9.5 | SV6.6 7.62,71.12 19.05,71.12 | 19.05,71.12 SV7.6 | 31.75,71.12 SV8.6 | 31.75,71.12 19.05,71.12 | 31.75,71.12 46.99,71.12 SV9.6 46.99,73.66 46.99,77.47 78.74,77.47 80.01,76.2 IC11.2 80.01,73.66 81.28,72.39 86.36,72.39 C4.2 | 24.13,21.59 15.24,21.59 13.97,22.86 IC4.5 | 24.13,21.59 25.4,22.86 IC3.5 | 38.1,21.59 39.37,22.86 IC2.5 | 38.1,21.59 24.13,21.59 | 38.1,21.59 52.07,21.59 53.34,22.86 IC1.5 55.88,22.86 58.42,25.4 76.2,25.4 77.47,26.67 IO_IC.10 83.82,26.67 87.63,22.86 95.25,22.86 JP1.5 | SV5.6 12.7,10.16 24.13,10.16 | 24.13,10.16 SV4.6 | 24.13,10.16 38.1,10.16 SV3.6 40.64,10.16 54.61,10.16 | 73.66,2.54 74.93,3.81 IC8.13 | 73.66,2.54 71.12,2.54 69.85,3.81 IC8.11 | 54.61,10.16 55.88,11.43 62.23,11.43 IC8.7 | 54.61,10.16 SV2.6 | JP1.1 96.52,2.54 73.66,2.54
  pour Bottom: 0,80.01 100.33,80.01 100.33,0 0,0
  pour Top: 0,80.01 0,0 100.33,0 100.33,80.01

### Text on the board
Bottom: design by | (c) 2009, | Arjan Scherpenisse
tNames: VGA Control Board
